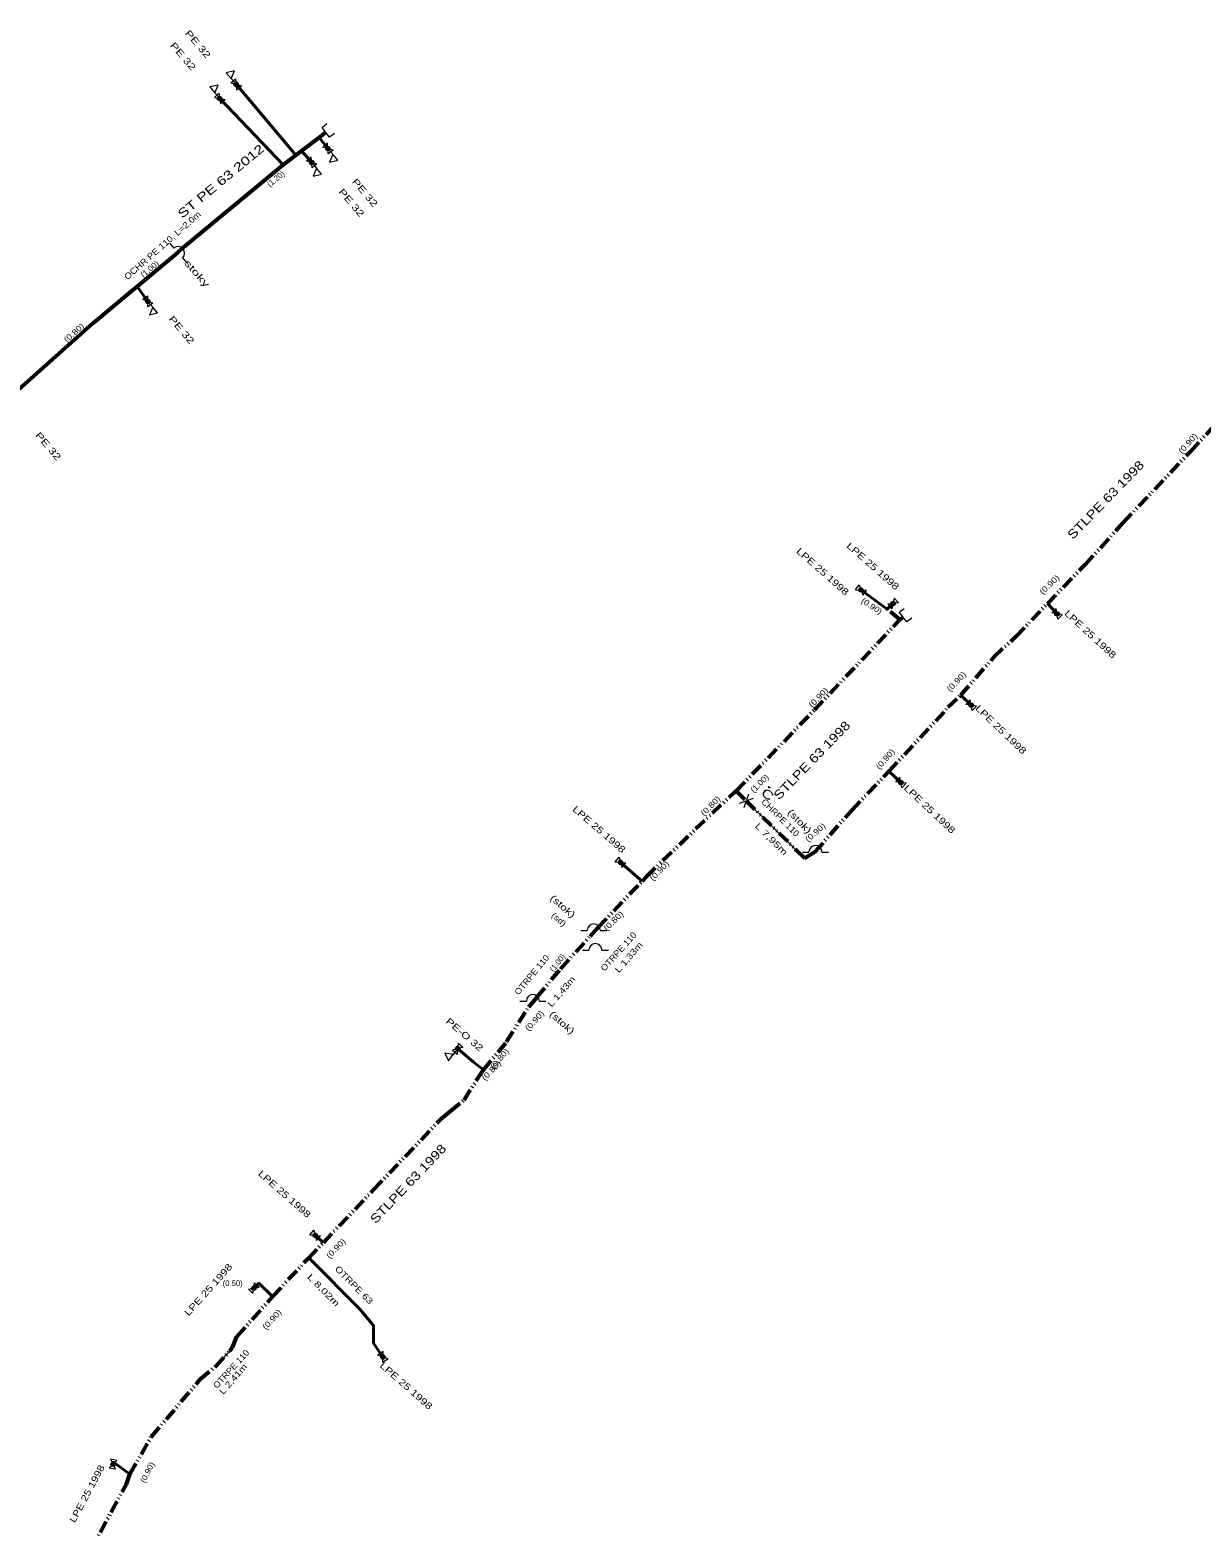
# Model space of a CAD drawing. Extents: x -648036 to -642998, y -1161549 to -1158141.
# Drawn here: x -644467.9 to -644334.7, y -1159942.6 to -1159772.3 of the extents above; entities that cross this region are included whole.
import ezdxf
from ezdxf.enums import TextEntityAlignment as Align

# ---------------------------------------------------------------- set-up
doc = ezdxf.new("R2010")
doc.units = 0
doc.header["$LTSCALE"] = 0.28
doc.linetypes.add('DASH_DOUBLE_DOT', pattern=[9.2, 5, -1.2, 0.3, -1.2, 0.3, -1.2])
for name, color, linetype, lineweight in [('12', 7, 'DASH_DOUBLE_DOT', 40), ('14', 7, 'Continuous', 13), ('15', 7, 'Continuous', 13), ('19', 7, 'Continuous', 13), ('8', 7, 'Continuous', 53)]:
    doc.layers.add(name, color=color, linetype=linetype, lineweight=lineweight)
for name, color, linetype in [('20', 7, 'Continuous'), ('22', 7, 'Continuous'), ('24', 7, 'Continuous'), ('27', 7, 'Continuous'), ('28', 7, 'Continuous')]:
    doc.layers.add(name, color=color, linetype=linetype)

msp = doc.modelspace()

# ---------------------------------------------------------------- linework, layer by layer
at = {"layer": '12', "linetype": 'Continuous'}
for p, q in [((-644437.67, -1159786.58), (-644444.46, -1159778.53)), ((-644439.09, -1159787.68), (-644446.33, -1159780.15)), ((-644435.01, -1159784.58), (-644434.01, -1159785.84)), ((-644437.01, -1159786.09), (-644435.86, -1159787.43)), ((-644455.72, -1159801.55), (-644454.51, -1159803.23)), ((-644370.38, -1159838.23), (-644373.36, -1159836.06)), ((-644370.38, -1159838.23), (-644369.71, -1159837.6)), ((-644352.15, -1159837.6), (-644351.05, -1159838.77)), ((-644361.99, -1159848.03), (-644360.81, -1159849.17)), ((-644370.18, -1159856.68), (-644368.82, -1159857.96)), ((-644400.73, -1159867.05), (-644398.25, -1159869.18))]:
    msp.add_line(p, q, dxfattribs=at)
at = {"layer": '12'}
msp.add_line((-644434.52, -1159910.29), (-644435.46, -1159909.49), dxfattribs=at)
at = {"layer": '12', "linetype": 'Continuous'}
for points in [[(-644419.25, -1159888.25), (-644419.07, -1159888.39), (-644417.49, -1159889.74), (-644416.32, -1159890.66)], [(-644436.23, -1159912.09), (-644436.03, -1159912.19), (-644430.4, -1159917.9), (-644428.82, -1159919.75), (-644428.82, -1159921.74), (-644427.75, -1159923.33)], [(-644440.31, -1159916.43), (-644441.89, -1159914.93), (-644442.45, -1159915.51)], [(-644458.46, -1159935.53), (-644458.42, -1159935.31), (-644456.54, -1159936.66)]]:
    msp.add_lwpolyline(points, dxfattribs=at)
at = {"layer": '14'}
for p, q in [((-644380.72, -1159865.65), (-644386.43, -1159860.07)), ((-644404.18, -1159875.44), (-644403.29, -1159874.45)), ((-644410.24, -1159882.39), (-644411.15, -1159883.49)), ((-644430.4, -1159917.9), (-644436.03, -1159912.19)), ((-644445.18, -1159922.61), (-644446.8, -1159924.4))]:
    msp.add_line(p, q, dxfattribs=at)
msp.add_lwpolyline([(-644451.8, -1159798.28), (-644451.09, -1159797.68), (-644450.3, -1159796.96)], dxfattribs=at)
at = {"layer": '15'}
for p, q in [((-644445.057, -1159778.374), (-644444.513, -1159777.915)), ((-644445.057, -1159778.374), (-644443.863, -1159778.686)), ((-644444.46, -1159778.53), (-644445.015, -1159777.877)), ((-644444.513, -1159777.915), (-644444.408, -1159779.144)), ((-644446.936, -1159780.033), (-644446.423, -1159779.54)), ((-644446.936, -1159780.033), (-644445.724, -1159780.267)), ((-644446.33, -1159780.15), (-644446.885, -1159779.497)), ((-644446.423, -1159779.54), (-644446.238, -1159780.759)), ((-644446.238, -1159780.759), (-644445.724, -1159780.267)), ((-644444.408, -1159779.144), (-644443.863, -1159778.686)), ((-644434.044, -1159785.225), (-644434.602, -1159785.667)), ((-644433.976, -1159786.456), (-644434.044, -1159785.225)), ((-644435.917, -1159786.816), (-644436.458, -1159787.279)), ((-644435.802, -1159788.044), (-644435.917, -1159786.816)), ((-644433.418, -1159786.013), (-644434.602, -1159785.667)), ((-644434.01, -1159785.84), (-644433.455, -1159786.493)), ((-644433.418, -1159786.013), (-644433.976, -1159786.456)), ((-644435.262, -1159787.581), (-644436.458, -1159787.279)), ((-644435.86, -1159787.43), (-644435.305, -1159788.083)), ((-644435.262, -1159787.581), (-644435.802, -1159788.044)), ((-644452.034, -1159796.612), (-644451.548, -1159797.164)), ((-644450.568, -1159798.281), (-644450.085, -1159798.833)), ((-644454.515, -1159802.614), (-644455.093, -1159803.029)), ((-644453.927, -1159803.431), (-644455.093, -1159803.029)), ((-644454.504, -1159803.847), (-644454.515, -1159802.614)), ((-644454.51, -1159803.23), (-644453.955, -1159803.883)), ((-644453.927, -1159803.431), (-644454.504, -1159803.847)), ((-644373.977, -1159836.051), (-644373.558, -1159835.476)), ((-644373.977, -1159836.051), (-644372.743, -1159836.069)), ((-644373.558, -1159835.476), (-644373.163, -1159836.644)), ((-644373.163, -1159836.644), (-644372.743, -1159836.069)), ((-644369.099, -1159837.514), (-644370.32, -1159837.685)), ((-644370.32, -1159837.685), (-644369.833, -1159838.205)), ((-644369.587, -1159836.995), (-644369.833, -1159838.205)), ((-644369.587, -1159836.995), (-644369.099, -1159837.514)), ((-644351.135, -1159838.16), (-644351.655, -1159838.647)), ((-644350.964, -1159839.381), (-644351.135, -1159838.16)), ((-644350.445, -1159838.893), (-644351.655, -1159838.647)), ((-644350.445, -1159838.893), (-644350.964, -1159839.381)), ((-644360.924, -1159848.564), (-644361.42, -1159849.076)), ((-644360.2, -1159849.264), (-644361.42, -1159849.076)), ((-644360.695, -1159849.776), (-644360.924, -1159848.564)), ((-644360.2, -1159849.264), (-644360.695, -1159849.776)), ((-644383.899, -1159858.373), (-644383.864, -1159858.591)), ((-644383.644, -1159858.564), (-644383.864, -1159858.591)), ((-644368.942, -1159857.356), (-644369.431, -1159857.874)), ((-644368.209, -1159858.046), (-644369.431, -1159857.874)), ((-644368.697, -1159858.565), (-644368.942, -1159857.356)), ((-644368.209, -1159858.046), (-644368.697, -1159858.565)), ((-644385.634, -1159859.804), (-644387.225, -1159860.336)), ((-644386.159, -1159859.276), (-644386.7, -1159860.863)), ((-644401.344, -1159866.992), (-644400.88, -1159866.452)), ((-644401.344, -1159866.992), (-644400.116, -1159867.108)), ((-644400.88, -1159866.452), (-644400.58, -1159867.648)), ((-644400.58, -1159867.648), (-644400.116, -1159867.108)), ((-644380.025, -1159865.875), (-644379.29, -1159865.874)), ((-644377.804, -1159865.874), (-644377.07, -1159865.875)), ((-644405.245, -1159874.795), (-644404.51, -1159874.794)), ((-644403.024, -1159874.794), (-644402.29, -1159874.795)), ((-644405.055, -1159877.045), (-644404.32, -1159877.044)), ((-644402.834, -1159877.044), (-644402.1, -1159877.045)), ((-644412.165, -1159882.845), (-644411.43, -1159882.844)), ((-644409.944, -1159882.844), (-644409.21, -1159882.845)), ((-644418.655, -1159888.087), (-644419.845, -1159888.412)), ((-644419.845, -1159888.412), (-644419.295, -1159888.865)), ((-644419.25, -1159888.25), (-644419.771, -1159888.93)), ((-644419.205, -1159887.635), (-644419.295, -1159888.865)), ((-644419.205, -1159887.635), (-644418.655, -1159888.087)), ((-644436.075, -1159909.434), (-644435.613, -1159908.892)), ((-644436.075, -1159909.434), (-644434.845, -1159909.546)), ((-644435.613, -1159908.892), (-644435.308, -1159910.087)), ((-644435.308, -1159910.087), (-644434.845, -1159909.546)), ((-644443.056, -1159915.625), (-644441.845, -1159915.395)), ((-644442.544, -1159916.12), (-644443.056, -1159915.625)), ((-644442.544, -1159916.12), (-644442.356, -1159914.9)), ((-644441.845, -1159915.395), (-644442.356, -1159914.9)), ((-644427.735, -1159922.714), (-644428.327, -1159923.111)), ((-644427.173, -1159923.549), (-644428.327, -1159923.111)), ((-644427.764, -1159923.947), (-644427.735, -1159922.714)), ((-644427.173, -1159923.549), (-644427.764, -1159923.947)), ((-644458.9, -1159935.962), (-644458.02, -1159935.099)), ((-644458.02, -1159935.099), (-644458.72, -1159934.97)), ((-644458.2, -1159936.09), (-644458.72, -1159934.97)), ((-644458.2, -1159936.09), (-644458.9, -1159935.962))]:
    msp.add_line(p, q, dxfattribs=at)
for points in [[(-644446.885, -1159779.497), (-644446.513, -1159778.61), (-644447.448, -1159778.834)], [(-644445.015, -1159777.877), (-644444.643, -1159776.99), (-644445.578, -1159777.214)], [(-644433.455, -1159786.493), (-644433.827, -1159787.38), (-644432.892, -1159787.156)], [(-644435.305, -1159788.083), (-644435.677, -1159788.97), (-644434.742, -1159788.746)], [(-644453.955, -1159803.883), (-644454.327, -1159804.77), (-644453.392, -1159804.546)], [(-644419.771, -1159888.93), (-644420.716, -1159888.754), (-644420.301, -1159889.621)]]:
    msp.add_lwpolyline(points, close=True, dxfattribs=at)
for points in [[(-644433.261, -1159784.115), (-644433.817, -1159784.548), (-644434.683, -1159783.432), (-644434.126, -1159783)], [(-644367.581, -1159839.264), (-644368.137, -1159839.697), (-644369.003, -1159838.583), (-644368.447, -1159838.15)]]:
    msp.add_lwpolyline(points, dxfattribs=at)
for centre, start, end in [((-644451.0588, -1159797.7226), 312.54709, 131.1118), ((-644378.5474, -1159865.8746), 1.2748, 179.83951), ((-644403.7674, -1159874.7946), 1.2748, 179.83951), ((-644403.5774, -1159877.0446), 1.2748, 179.83951), ((-644410.6874, -1159882.8446), 1.2748, 179.83951)]:
    msp.add_arc(centre, 0.7431, start, end, dxfattribs=at)
at = {"layer": '19'}
for centre, radius in [((-644444.46, -1159778.53), 0.25), ((-644444.46, -1159778.53), 0.17), ((-644444.46, -1159778.53), 0.09), ((-644446.33, -1159780.15), 0.25), ((-644446.33, -1159780.15), 0.17), ((-644446.33, -1159780.15), 0.09), ((-644434.01, -1159785.84), 0.25), ((-644434.01, -1159785.84), 0.17), ((-644434.01, -1159785.84), 0.09), ((-644435.86, -1159787.43), 0.25), ((-644435.86, -1159787.43), 0.17), ((-644435.86, -1159787.43), 0.09), ((-644454.51, -1159803.23), 0.25), ((-644454.51, -1159803.23), 0.17), ((-644454.51, -1159803.23), 0.09), ((-644373.36, -1159836.06), 0.25), ((-644373.36, -1159836.06), 0.17), ((-644373.36, -1159836.06), 0.09), ((-644369.71, -1159837.6), 0.25), ((-644369.71, -1159837.6), 0.17), ((-644369.71, -1159837.6), 0.09), ((-644351.05, -1159838.77), 0.25), ((-644351.05, -1159838.77), 0.17), ((-644351.05, -1159838.77), 0.09), ((-644360.81, -1159849.17), 0.25), ((-644360.81, -1159849.17), 0.17), ((-644360.81, -1159849.17), 0.09), ((-644368.82, -1159857.96), 0.25), ((-644368.82, -1159857.96), 0.17), ((-644368.82, -1159857.96), 0.09), ((-644400.73, -1159867.05), 0.25), ((-644400.73, -1159867.05), 0.17), ((-644400.73, -1159867.05), 0.09), ((-644419.25, -1159888.25), 0.25), ((-644419.25, -1159888.25), 0.17), ((-644419.25, -1159888.25), 0.09), ((-644435.46, -1159909.49), 0.25), ((-644435.46, -1159909.49), 0.17), ((-644435.46, -1159909.49), 0.09), ((-644442.45, -1159915.51), 0.25), ((-644442.45, -1159915.51), 0.17), ((-644442.45, -1159915.51), 0.09), ((-644427.75, -1159923.33), 0.25), ((-644427.75, -1159923.33), 0.17), ((-644427.75, -1159923.33), 0.09), ((-644458.46, -1159935.53), 0.25), ((-644458.46, -1159935.53), 0.17), ((-644458.46, -1159935.53), 0.09)]:
    msp.add_circle(centre, radius, dxfattribs=at)
at = {"layer": '8', "linetype": 'DASH_DOUBLE_DOT'}
for p, q in [((-644368.93, -1159839.42), (-644370.38, -1159838.23)), ((-644368.93, -1159839.42), (-644368.57, -1159839.14)), ((-644387.56, -1159858.9), (-644386.43, -1159860.07))]:
    msp.add_line(p, q, dxfattribs=at)
at = {"layer": '8'}
for points in [[(-644455.72, -1159801.55), (-644451.8, -1159798.28), (-644451.09, -1159797.68), (-644450.3, -1159796.96), (-644439.09, -1159787.68), (-644437.67, -1159786.58), (-644437.01, -1159786.09), (-644435.01, -1159784.58), (-644434.25, -1159783.99)], [(-644470.98, -1159814.83), (-644460.73, -1159805.69), (-644456.33, -1159802.04), (-644455.72, -1159801.55)]]:
    msp.add_lwpolyline(points, dxfattribs=at)
at = {"layer": '8', "linetype": 'DASH_DOUBLE_DOT'}
for points in [[(-644352.15, -1159837.6), (-644347.86, -1159833.18), (-644343.52, -1159828.39), (-644335.86, -1159820.29), (-644329.5, -1159813.36), (-644320.36, -1159802.94), (-644318.34, -1159800.96), (-644318.09, -1159800.67)], [(-644361.99, -1159848.03), (-644358.23, -1159843.69), (-644355.73, -1159841.36), (-644352.15, -1159837.6)], [(-644387.56, -1159858.9), (-644378.65, -1159849.71), (-644368.93, -1159839.42)], [(-644370.18, -1159856.68), (-644363.43, -1159849.41), (-644361.99, -1159848.03)], [(-644386.43, -1159860.07), (-644380.72, -1159865.65), (-644379.77, -1159866.58), (-644378.6, -1159865.87), (-644374.41, -1159861.11), (-644370.18, -1159856.68)], [(-644398.25, -1159869.18), (-644397.78, -1159868.66), (-644390.27, -1159861.45), (-644387.56, -1159858.9)], [(-644416.32, -1159890.66), (-644413.68, -1159887.47), (-644411.15, -1159883.49), (-644410.24, -1159882.39), (-644407.55, -1159879.16), (-644404.18, -1159875.44), (-644403.29, -1159874.45), (-644398.25, -1159869.18)], [(-644434.52, -1159910.29), (-644428.81, -1159904.28), (-644421.1, -1159896.19), (-644420.04, -1159895.34), (-644418.52, -1159894.12), (-644416.84, -1159891.45), (-644416.32, -1159890.66)], [(-644456.54, -1159936.66), (-644454.09, -1159932.38), (-644448.54, -1159925.87), (-644446.8, -1159924.4), (-644445.18, -1159922.61), (-644444.86, -1159922.26), (-644444.36, -1159921), (-644440.31, -1159916.43), (-644436.23, -1159912.09), (-644434.52, -1159910.29)], [(-644465.76, -1159953.71), (-644464.14, -1159950.83), (-644463.17, -1159949.19), (-644462.39, -1159947.85), (-644456.94, -1159937.79), (-644456.54, -1159936.66)]]:
    msp.add_lwpolyline(points, dxfattribs=at)

# ---------------------------------------------------------------- texts
at = {"layer": '15', "width": 1.4}
msp.add_text('C', height=1, rotation=323.148, dxfattribs=at).set_placement((-644384.2794, -1159859.7212), align=Align.CENTER)
at = {"layer": '20'}
for s, rotation, width, p in [('ST PE 63 2012', 39.619, 1.35, (-644445.8793, -1159789.9331)), ('STLPE 63 1998', 45.837, 1.25, (-644345.1509, -1159826.1499)), ('STLPE 63 1998', 45.837, 1.25, (-644378.5909, -1159855.7899)), ('STLPE 63 1998', 46.41, 1.25, (-644424.5279, -1159903.9662))]:
    msp.add_text(s, height=1, rotation=rotation, dxfattribs=dict(at, width=width)).set_placement(p, align=Align.CENTER)
at = {"layer": '22'}
for s, rotation, width, p in [('PE 32', 310.365, 1.4, (-644449.091, -1159774.1956)), ('PE 32', 310.365, 1.4, (-644450.787, -1159775.5826)), ('PE 32', 310.269, 1.4, (-644431.6179, -1159792.2451)), ('PE 32', 310.269, 1.4, (-644430.0929, -1159791.1001)), ('PE 32', 310.314, 1.4, (-644450.951, -1159806.7129)), ('PE 32', 310.328, 1.4, (-644466.122, -1159819.9373)), ('LPE 25 1998', 318.565, 1.3, (-644377.9642, -1159834.2429)), ('LPE 25 1998', 318.565, 1.3, (-644372.2442, -1159833.6329)), ('LPE 25 1998', 317.419, 1.3, (-644347.5052, -1159841.3624)), ('LPE 25 1998', 316.273, 1.3, (-644357.6952, -1159852.2128)), ('LPE 25 1998', 316.846, 1.3, (-644365.8005, -1159861.2677)), ('LPE 25 1998', 319.138, 1.3, (-644403.4098, -1159863.5783)), ('PE-O 32', 319.372, 1.35, (-644418.7062, -1159886.9292)), ('LPE 25 1998', 318.565, 1.3, (-644439.2042, -1159905.0629)), ('LPE 25 1998', 48.128, 1.3, (-644447.3435, -1159915.9213)), ('LPE 25 1998', 318.565, 1.3, (-644425.3542, -1159926.8929)), ('LPE 25 1998', 61.879, 1.25, (-644461.0929, -1159939.0572))]:
    msp.add_text(s, height=0.75, rotation=rotation, dxfattribs=dict(at, width=width)).set_placement(p, align=Align.CENTER)
at = {"layer": '24'}
for s, rotation, width, p in [('OCHR PE 110, L=2.0m', 41.272, 1.15, (-644452.6104, -1159797.1313)), ('CHRPE 110', 315.127, 1.1, (-644382.7689, -1159862.2114)), ('L 7,95m', 315.127, 1.4, (-644383.7964, -1159864.6531)), ('OTRPE 110', 48.128, 1.1, (-644400.6839, -1159877.4296)), ('L 1,33m', 49.274, 1.25, (-644399.5169, -1159878.0784)), ('OTRPE 110', 50.42, 1.1, (-644410.5409, -1159880.067)), ('L 1,43m', 49.274, 1.25, (-644407.1769, -1159881.9804)), ('OTRPE 63', 314.554, 1.25, (-644431.2936, -1159915.3789)), ('L 8,02m', 314.554, 1.4, (-644434.769, -1159915.9724)), ('OTRPE 110', 47.555, 1.1, (-644444.7688, -1159924.9352)), ('L 2,41m', 49.274, 1.25, (-644444.5369, -1159926.0704))]:
    msp.add_text(s, height=0.7, rotation=rotation, dxfattribs=dict(at, width=width)).set_placement(p, align=Align.CENTER)
at = {"layer": '27'}
for s, rotation, p in [('(1.20)', 39.619, (-644439.7412, -1159789.5331)), ('(1.00)', 52.139, (-644407.6374, -1159878.672))]:
    msp.add_text(s, height=0.65, rotation=rotation, dxfattribs=at).set_placement(p, align=Align.CENTER)
for s, rotation, width, p in [('(1.00)', 39.834, 1.05, (-644454.0892, -1159799.7987)), ('(0.80)', 41.724, 1.2, (-644462.6928, -1159807.0383)), ('(0.90)', 48.128, 1.2, (-644335.9154, -1159819.6014)), ('(0.90)', 43.545, 1.2, (-644351.6919, -1159835.6788)), ('(0.90)', 326.586, 1.15, (-644372.308, -1159838.1502)), ('(0.90)', 46.41, 1.2, (-644362.2682, -1159846.7011)), ('(0.90)', 46.41, 1.2, (-644377.9682, -1159848.5111)), ('(0.90)', 48.701, 1.2, (-644370.351, -1159855.514)), ('(1.00)', 45.264, 1.1, (-644384.6701, -1159858.2997)), ('(0.80)', 45.264, 1.2, (-644390.2493, -1159860.8577)), ('(0.90)', 41.826, 1.2, (-644378.3407, -1159863.8855)), ('(0.90)', 45.837, 1.2, (-644396.0724, -1159868.2379)), ('(sd)', 318.565, 1.25, (-644407.9476, -1159873.7882)), ('(0.80)', 45.264, 1.2, (-644401.2893, -1159873.9377)), ('(0.90)', 48.701, 1.2, (-644410.261, -1159885.284)), ('(0.80)', 50.393, 1.2, (-644414.2327, -1159889.6042)), ('(0.80)', 46.41, 1.2, (-644415.1801, -1159890.9541)), ('(0.90)', 46.41, 1.2, (-644432.8782, -1159911.2011)), ('(0.90)', 48.128, 1.2, (-644440.1454, -1159919.2714)), ('(0.90)', 63.025, 1.1, (-644454.2822, -1159936.5959))]:
    msp.add_text(s, height=0.65, rotation=rotation, dxfattribs=dict(at, width=width)).set_placement(p, align=Align.CENTER)
msp.add_text('(0.50)', height=0.65, dxfattribs=at).set_placement((-644444.85, -1159915.26), align=Align.CENTER)
at = {"layer": '28'}
for s, rotation, width, p in [('stoky', 311.272, 1.6, (-644449.1942, -1159800.3086)), ('(stok)', 313.981, 1.35, (-644380.6109, -1159862.6316)), ('(stok)', 319.138, 1.35, (-644407.5378, -1159872.3351)), ('(stok)', 318.565, 1.35, (-644407.6162, -1159885.5531))]:
    msp.add_text(s, height=0.75, rotation=rotation, dxfattribs=dict(at, width=width)).set_placement(p, align=Align.CENTER)

doc.saveas('drawing.dxf')
